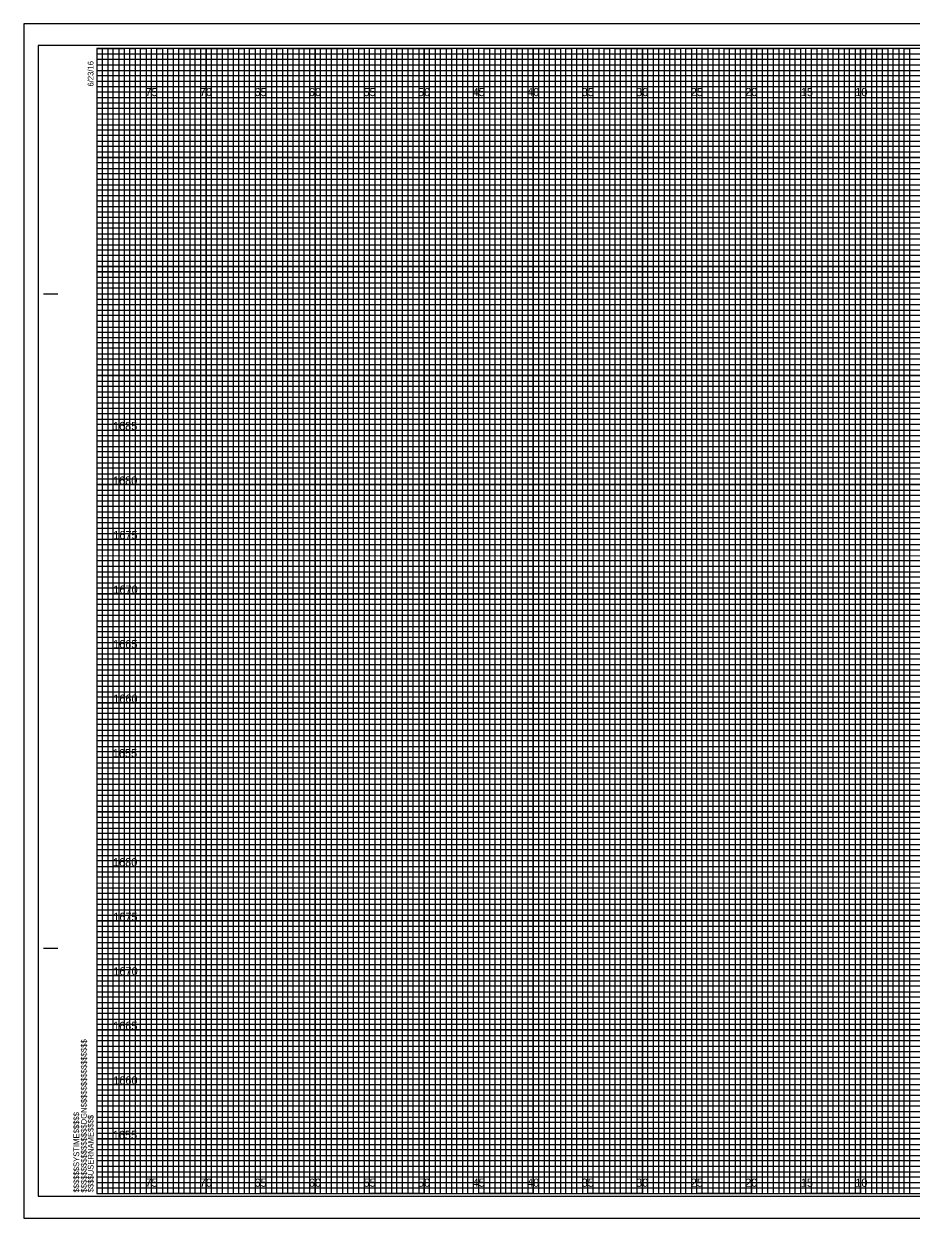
# Model space of a CAD drawing. Extents: x -73 to 95, y 6 to 446.
# Drawn here: x -73.1 to 8.2, y 226.1 to 335.6 of the extents above; entities that cross this region are included whole.
import ezdxf

# ---------------------------------------------------------------- set-up
doc = ezdxf.new("R2010")
doc.units = 0
for name, color, linetype in [('Exist CMT Alignment Centerline', 7, 'Continuous'), ('Prop Horizontal Alignment', 7, 'Continuous'), ('Prop XS DDE', 7, 'Continuous'), ('Raster_Level_0', 7, 'Continuous'), ('Sheet Cross Section CELL', 7, 'Continuous'), ('Sheet Cross Section Grid Minor 1 CELL', 7, 'Continuous'), ('Sheet Cross Section Grid Minor 2 CELL', 7, 'Continuous'), ('Sheet Cutting Line CELL', 7, 'Continuous'), ('Sheet DOT Grid CELL', 7, 'Continuous'), ('Sheet Plot Border Inside CELL', 7, 'Continuous'), ('Sheet Plot Border Outside CELL', 7, 'Continuous')]:
    doc.layers.add(name, color=color, linetype=linetype)

msp = doc.modelspace()

# ---------------------------------------------------------------- linework, layer by layer
at = {"layer": 'Exist CMT Alignment Centerline'}
for p, q in [((-61.4, 333.4), (-66.4, 333.4)), ((-61.4, 228.4), (-61.4, 333.4)), ((-51.4, 333.4), (-56.4, 333.4)), ((-56.4, 333.4), (-56.4, 228.4)), ((-51.4, 228.4), (-51.4, 333.4)), ((-41.4, 333.4), (-46.4, 333.4)), ((-46.4, 333.4), (-46.4, 228.4)), ((-41.4, 228.4), (-41.4, 333.4)), ((-31.4, 333.4), (-36.4, 333.4)), ((-36.4, 333.4), (-36.4, 228.4)), ((-31.4, 228.4), (-31.4, 333.4)), ((-21.4, 333.4), (-26.4, 333.4)), ((-26.4, 333.4), (-26.4, 228.4)), ((-21.4, 228.4), (-21.4, 333.4)), ((-11.4, 333.4), (-16.4, 333.4)), ((-16.4, 333.4), (-16.4, 228.4)), ((-11.4, 228.4), (-11.4, 333.4)), ((-1.4, 333.4), (-6.4, 333.4)), ((-6.4, 333.4), (-6.4, 228.4)), ((-1.4, 228.4), (-1.4, 333.4)), ((8.6, 333.4), (3.6, 333.4)), ((3.6, 333.4), (3.6, 228.4)), ((-56.4, 228.4), (-61.4, 228.4)), ((-46.4, 228.4), (-51.4, 228.4)), ((-36.4, 228.4), (-41.4, 228.4)), ((-26.4, 228.4), (-31.4, 228.4)), ((-16.4, 228.4), (-21.4, 228.4)), ((-6.4, 228.4), (-11.4, 228.4)), ((3.6, 228.4), (-1.4, 228.4))]:
    msp.add_line(p, q, dxfattribs=at)
for points in [[(-66.4, 328.4), (93.6, 328.4), (93.6, 323.4), (-66.4, 323.4)], [(-66.4, 318.4), (93.6, 318.4), (93.6, 313.4), (-66.4, 313.4)], [(-66.4, 308.4), (93.6, 308.4), (93.6, 303.4), (-66.4, 303.4)], [(-66.4, 298.4), (93.6, 298.4), (93.6, 293.4), (-66.4, 293.4)], [(-66.4, 288.4), (93.6, 288.4), (93.6, 283.4), (-66.4, 283.4)], [(-66.4, 278.4), (93.6, 278.4), (93.6, 273.4), (-66.4, 273.4)], [(-66.4, 268.4), (93.6, 268.4), (93.6, 263.4), (-66.4, 263.4)], [(-66.4, 258.4), (93.6, 258.4), (93.6, 253.4), (-66.4, 253.4)], [(-66.4, 248.4), (93.6, 248.4), (93.6, 243.4), (-66.4, 243.4)], [(-66.4, 238.4), (93.6, 238.4), (93.6, 233.4), (-66.4, 233.4)]]:
    msp.add_lwpolyline(points, dxfattribs=at)
at = {"layer": 'Prop XS DDE'}
for points in [[(-66.4, 333.4), (-63.9, 333.4), (-63.9, 228.4), (-58.9, 228.4), (-58.9, 333.4), (-53.9, 333.4), (-53.9, 228.4), (-48.9, 228.4), (-48.9, 333.4), (-43.9, 333.4), (-43.9, 228.4), (-38.9, 228.4), (-38.9, 333.4), (-33.9, 333.4), (-33.9, 228.4), (-28.9, 228.4), (-28.9, 333.4), (-23.9, 333.4), (-23.9, 228.4), (-18.9, 228.4), (-18.9, 333.4), (-13.9, 333.4), (-13.9, 228.4), (-8.9, 228.4), (-8.9, 333.4), (-3.9, 333.4), (-3.9, 228.4), (1.1, 228.4), (1.1, 333.4), (6.1, 333.4), (6.1, 228.4), (11.1, 228.4)], [(-66.4, 330.9), (71.1, 330.9)], [(-66.4, 320.9), (93.6, 320.9), (93.6, 325.9), (-66.4, 325.9)], [(-66.4, 310.9), (93.6, 310.9), (93.6, 315.9), (-66.4, 315.9)], [(-66.4, 300.9), (93.6, 300.9), (93.6, 305.9), (-66.4, 305.9)], [(-66.4, 290.9), (93.6, 290.9), (93.6, 295.9), (-66.4, 295.9)], [(-66.4, 280.9), (93.6, 280.9), (93.6, 285.9), (-66.4, 285.9)], [(-66.4, 270.9), (93.6, 270.9), (93.6, 275.9), (-66.4, 275.9)], [(-66.4, 260.9), (93.6, 260.9), (93.6, 265.9), (-66.4, 265.9)], [(-66.4, 250.9), (93.6, 250.9), (93.6, 255.9), (-66.4, 255.9)], [(-66.4, 240.9), (93.6, 240.9), (93.6, 245.9), (-66.4, 245.9)], [(-66.4, 230.9), (93.6, 230.9), (93.6, 235.9), (-66.4, 235.9)]]:
    msp.add_lwpolyline(points, dxfattribs=at)
at = {"layer": 'Sheet Cross Section CELL'}
for p, q in [((-71.3, 310.9), (-70.05, 310.9)), ((-71.25, 310.9), (-70, 310.9)), ((-71.3, 250.9), (-70.05, 250.9)), ((-71.25, 250.9), (-70, 250.9)), ((-66.4, 228.4), (-66.4, 228.4)), ((-66.4, 228.4), (-66.4, 228.4)), ((-66.4, 228.4), (-66.4, 228.4)), ((-66.4, 228.4), (-66.4, 228.4)), ((-66.4, 228.4), (-66.4, 228.4)), ((-66.4, 228.4), (-66.4, 228.4)), ((-66.4, 228.4), (-66.4, 228.4))]:
    msp.add_line(p, q, dxfattribs=at)
msp.add_lwpolyline([(93.6, 333.4), (-66.4, 333.4), (-66.4, 228.4), (93.6, 228.4)], close=True, dxfattribs=at)
at = {"layer": 'Sheet Cross Section Grid Minor 1 CELL'}
for p, q in [((-66.4, 332.9), (63.6, 332.9)), ((63.6, 332.39), (-66.4, 332.39)), ((-66.4, 332.39), (-66.4, 331.9)), ((-66.4, 331.9), (63.6, 331.9)), ((63.6, 331.34), (-66.4, 331.34)), ((-66.4, 331.34), (-66.4, 330.4)), ((-66.4, 330.4), (93.6, 330.4))]:
    msp.add_line(p, q, dxfattribs=at)
for points in [[(-66.4, 329.9), (68.6, 329.9), (93.6, 329.9), (93.6, 329.4), (-66.4, 329.4)], [(-66.4, 328.9), (93.6, 328.9), (93.6, 327.9), (-66.4, 327.9)], [(-66.4, 327.4), (93.6, 327.4), (93.6, 326.9), (-66.4, 326.89)], [(-66.4, 326.4), (93.6, 326.4), (93.6, 325.4), (-66.4, 325.4)], [(-66.4, 324.9), (93.6, 324.9), (93.6, 324.4), (-66.4, 324.4)], [(-66.4, 323.9), (93.6, 323.9), (93.6, 322.9), (-66.4, 322.9)], [(-66.4, 322.4), (93.6, 322.4), (93.6, 321.9), (-66.4, 321.9)], [(-66.4, 321.4), (93.6, 321.4), (93.6, 320.4), (-66.4, 320.4)], [(-66.4, 319.9), (93.6, 319.9), (93.6, 319.4), (-66.4, 319.4)], [(-66.4, 318.9), (93.6, 318.9), (93.6, 317.9), (-66.4, 317.9)], [(-66.4, 317.4), (93.6, 317.4), (93.6, 316.9), (-66.4, 316.9)], [(-66.4, 316.4), (93.6, 316.4), (93.6, 315.37), (93.6, 314.9), (93.6, 314.4), (-66.4, 314.4)], [(-66.4, 315.4), (93.6, 315.4), (93.6, 314.9), (-66.4, 314.9)], [(-66.4, 313.9), (93.6, 313.9), (93.6, 312.9), (-66.4, 312.91)], [(-66.4, 312.91), (93.6, 312.9), (93.6, 312.4), (-66.4, 312.4)], [(-66.4, 311.9), (93.6, 311.9), (93.6, 311.4), (-66.4, 311.4)], [(-66.4, 310.4), (93.6, 310.4), (93.6, 309.9), (-66.4, 309.9)], [(-66.4, 309.4), (93.6, 309.4), (93.6, 308.9), (-66.4, 308.9)], [(-66.43, 307.84), (93.6, 307.84), (93.6, 307.34), (-66.43, 307.34)], [(-66.4, 306.9), (93.6, 306.9), (93.6, 306.4), (-66.4, 306.4)], [(-66.4, 305.4), (93.6, 305.4), (93.6, 304.9), (-66.4, 304.9)], [(-66.4, 304.4), (93.6, 304.4), (93.6, 303.9), (-66.4, 303.9)], [(-66.4, 302.9), (93.6, 302.9), (93.6, 302.4), (-66.4, 302.4)], [(-66.4, 301.9), (93.6, 301.9), (93.6, 301.4), (-66.4, 301.4)], [(-66.4, 300.4), (93.6, 300.4), (93.6, 299.9), (-66.4, 299.9)], [(-66.4, 299.4), (93.6, 299.4), (93.6, 298.9), (-66.4, 298.9)], [(-66.4, 297.9), (93.6, 297.9), (93.6, 297.39), (-66.4, 297.4)], [(-66.4, 296.9), (93.6, 296.9), (93.6, 296.4), (-66.4, 296.4)], [(-66.4, 295.4), (93.6, 295.4), (93.6, 294.9), (-66.4, 294.9)], [(-66.4, 294.4), (93.6, 294.4), (93.6, 293.9), (-66.4, 293.9)], [(-66.4, 292.9), (93.6, 292.9), (93.6, 292.4), (-66.4, 292.4)], [(-66.4, 291.9), (93.6, 291.9), (93.6, 291.4), (-66.4, 291.4)], [(-66.4, 290.4), (93.6, 290.4), (93.6, 289.9), (-66.4, 289.9)], [(-66.4, 289.4), (93.6, 289.4), (93.6, 288.9), (-66.4, 288.9)], [(-66.4, 287.9), (93.6, 287.9), (93.6, 287.4), (-66.4, 287.4)], [(-66.4, 286.89), (93.64, 286.85), (93.6, 286.4), (-66.4, 286.4)], [(-66.4, 285.4), (93.6, 285.4), (93.6, 284.9), (-66.4, 284.9)], [(-66.4, 284.4), (93.6, 284.4), (93.6, 283.9), (-66.4, 283.9)], [(-66.4, 282.9), (93.6, 282.9), (93.6, 282.4), (-66.4, 282.4)], [(-66.4, 281.9), (93.6, 281.9), (93.6, 281.4), (-66.4, 281.4)], [(-66.4, 280.4), (93.6, 280.4), (93.6, 279.9), (-66.4, 279.9)], [(-66.4, 279.4), (93.6, 279.4), (93.6, 278.9), (-66.4, 278.9)], [(-66.4, 277.9), (93.6, 277.9), (93.6, 277.4), (-66.4, 277.4)], [(-66.4, 276.9), (93.6, 276.9), (93.6, 276.4), (-66.4, 276.4)], [(-66.4, 275.4), (93.6, 275.4), (93.6, 274.9), (-66.4, 274.9)], [(-66.4, 274.4), (93.6, 274.4), (93.6, 273.9), (-66.4, 273.9)], [(-66.4, 272.9), (93.6, 272.9), (93.6, 272.4), (-66.4, 272.4)], [(-66.4, 271.9), (93.6, 271.9), (93.6, 271.4), (-66.4, 271.4)], [(-66.4, 270.4), (93.6, 270.4), (93.6, 269.9), (-66.4, 269.9)], [(-66.4, 269.4), (93.6, 269.4), (93.6, 268.9), (-66.4, 268.9)], [(-66.4, 267.9), (93.6, 267.9), (93.6, 267.39), (-66.4, 267.4)], [(-66.4, 266.9), (93.6, 266.9), (93.6, 266.4), (-66.4, 266.4)], [(-66.4, 265.4), (93.6, 265.4), (93.6, 264.9), (-66.4, 264.9)], [(-66.4, 264.4), (93.6, 264.4), (93.6, 263.9), (-66.4, 263.9)], [(-66.4, 262.9), (93.6, 262.9), (93.6, 262.4), (-66.4, 262.4)], [(-66.4, 261.9), (93.6, 261.9), (93.6, 261.4), (-66.4, 261.4)], [(-66.4, 260.4), (93.6, 260.4), (93.6, 259.9), (-66.4, 259.9)], [(-66.4, 259.4), (93.6, 259.4), (93.6, 258.9), (-66.4, 258.9)], [(-66.4, 257.9), (93.6, 257.9), (93.6, 257.4), (-66.4, 257.4)], [(-66.4, 256.89), (93.64, 256.85), (93.6, 256.4), (-66.4, 256.4)], [(-66.4, 255.4), (93.6, 255.4), (93.6, 254.9), (-66.4, 254.9)], [(-66.4, 254.4), (93.6, 254.4), (93.6, 253.9), (-66.4, 253.9)], [(-66.4, 252.9), (93.6, 252.9), (93.6, 252.4), (-66.4, 252.4)], [(-66.4, 251.9), (93.6, 251.9), (93.6, 251.4), (-66.4, 251.4)], [(-66.4, 250.4), (93.6, 250.4), (93.6, 249.9), (-66.4, 249.9)], [(-66.4, 249.4), (93.6, 249.4), (93.6, 248.9), (-66.4, 248.9)], [(-66.4, 247.9), (93.6, 247.9), (93.6, 247.4), (-66.4, 247.4)], [(-66.4, 246.9), (93.6, 246.9), (93.6, 246.4), (-66.4, 246.4)], [(-66.4, 245.4), (93.6, 245.4), (93.6, 244.9), (-66.4, 244.9)], [(-66.4, 244.4), (93.6, 244.4), (93.6, 243.9), (-66.4, 243.9)], [(-66.4, 242.9), (93.6, 242.9), (93.6, 242.4), (-66.4, 242.4)], [(-66.4, 241.9), (93.6, 241.9), (93.6, 241.4), (-66.4, 241.4)], [(-66.4, 240.4), (93.6, 240.4), (93.6, 239.9), (-66.4, 239.9)], [(-66.4, 239.4), (93.6, 239.4), (93.6, 238.9), (-66.4, 238.9)], [(-66.4, 237.9), (93.6, 237.9), (93.6, 237.4), (-66.4, 237.4)], [(-66.4, 236.9), (93.6, 236.9), (93.6, 236.4), (-66.4, 236.4)], [(-66.4, 235.4), (93.6, 235.4), (93.6, 234.9), (-66.4, 234.9)], [(-66.4, 234.4), (93.6, 234.4), (93.6, 233.9), (-66.4, 233.9)], [(-66.4, 232.9), (93.6, 232.9), (93.6, 232.4), (-66.4, 232.4)], [(-66.4, 231.9), (93.6, 231.9), (93.6, 231.4), (-66.4, 231.4)], [(-66.4, 230.4), (93.6, 230.4), (93.6, 229.9), (-66.4, 229.9)], [(-66.4, 229.4), (93.6, 229.4), (93.6, 228.9), (-66.4, 228.9)]]:
    msp.add_lwpolyline(points, dxfattribs=at)
at = {"layer": 'Sheet Cross Section Grid Minor 2 CELL'}
for points in [[(-66.4, 228.4), (-65.9, 228.4), (-65.9, 333.4), (-65.4, 333.4), (-65.4, 228.4)], [(-65.4, 228.4), (-64.9, 228.4), (-64.9, 333.4), (-64.4, 333.4), (-64.4, 228.4)], [(-63.9, 228.4), (-63.4, 228.4), (-63.4, 333.4), (-62.9, 333.4), (-62.9, 228.4)], [(-62.9, 228.4), (-62.4, 228.4), (-62.4, 333.4), (-61.9, 333.4), (-61.9, 228.4)], [(-61.4, 228.4), (-60.9, 228.4), (-60.9, 333.4), (-60.4, 333.4), (-60.4, 228.4)], [(-60.4, 228.4), (-59.9, 228.4), (-59.9, 333.4), (-59.4, 333.4), (-59.4, 228.4)], [(-58.9, 228.4), (-58.4, 228.4), (-58.4, 333.4), (-57.9, 333.4), (-57.9, 228.4)], [(-57.9, 228.4), (-57.4, 228.4), (-57.4, 333.4), (-56.9, 333.4), (-56.9, 228.4)], [(-56.4, 228.4), (-55.9, 228.4), (-55.9, 333.4), (-55.4, 333.4), (-55.4, 228.4)], [(-55.4, 228.4), (-54.9, 228.4), (-54.9, 333.4), (-54.4, 333.4), (-54.4, 228.4)], [(-53.9, 228.4), (-53.4, 228.4), (-53.4, 333.4), (-52.9, 333.4), (-52.9, 228.4)], [(-52.9, 228.4), (-52.4, 228.4), (-52.4, 333.4), (-51.9, 333.4), (-51.9, 228.4)], [(-51.4, 228.4), (-50.9, 228.4), (-50.9, 333.4), (-50.4, 333.4), (-50.4, 228.4)], [(-50.4, 228.4), (-49.9, 228.4), (-49.9, 333.4), (-49.4, 333.4), (-49.4, 228.4)], [(-48.9, 228.4), (-48.4, 228.4), (-48.4, 333.4), (-47.9, 333.4), (-47.9, 228.4)], [(-47.9, 228.4), (-47.4, 228.4), (-47.4, 333.4), (-46.9, 333.4), (-46.9, 228.4)], [(-46.4, 228.4), (-45.9, 228.4), (-45.9, 333.4), (-45.4, 333.4), (-45.4, 228.4)], [(-45.4, 228.4), (-44.9, 228.4), (-44.9, 333.4), (-44.4, 333.4), (-44.4, 228.4)], [(-43.9, 228.4), (-43.4, 228.4), (-43.4, 333.4), (-42.9, 333.4), (-42.9, 228.4)], [(-42.9, 228.4), (-42.4, 228.4), (-42.4, 333.4), (-41.9, 333.4), (-41.9, 228.4)], [(-41.4, 228.4), (-40.9, 228.4), (-40.9, 333.4), (-40.4, 333.4), (-40.4, 228.4)], [(-40.4, 228.4), (-39.9, 228.4), (-39.9, 333.4), (-39.4, 333.4), (-39.4, 228.4)], [(-38.9, 228.4), (-38.4, 228.4), (-38.4, 333.4), (-37.9, 333.4), (-37.9, 228.4)], [(-37.9, 228.4), (-37.4, 228.4), (-37.4, 333.4), (-36.9, 333.4), (-36.9, 228.4)], [(-36.4, 228.4), (-35.9, 228.4), (-35.9, 333.4), (-35.4, 333.4), (-35.4, 228.4)], [(-35.4, 228.4), (-34.9, 228.4), (-34.9, 333.4), (-34.4, 333.4), (-34.4, 228.4)], [(-33.9, 228.4), (-33.4, 228.4), (-33.4, 333.4), (-32.9, 333.4), (-32.9, 228.4)], [(-32.9, 228.4), (-32.4, 228.4), (-32.4, 333.4), (-31.9, 333.4), (-31.9, 228.4)], [(-31.4, 228.4), (-30.9, 228.4), (-30.9, 333.4), (-30.4, 333.4), (-30.4, 228.4)], [(-30.4, 228.4), (-29.9, 228.4), (-29.9, 333.4), (-29.4, 333.4), (-29.4, 228.4)], [(-28.9, 228.4), (-28.4, 228.4), (-28.4, 333.4), (-27.9, 333.4), (-27.9, 228.4)], [(-27.9, 228.4), (-27.4, 228.4), (-27.4, 333.4), (-26.9, 333.4), (-26.9, 228.4)], [(-26.4, 228.4), (-25.9, 228.4), (-25.9, 333.4), (-25.4, 333.4), (-25.4, 228.4)], [(-25.4, 228.4), (-24.9, 228.4), (-24.9, 333.4), (-24.4, 333.4), (-24.4, 228.4)], [(-23.9, 228.4), (-23.4, 228.4), (-23.4, 333.4), (-22.9, 333.4), (-22.9, 228.4)], [(-22.9, 228.4), (-22.4, 228.4), (-22.4, 333.4), (-21.9, 333.4), (-21.9, 228.4)], [(-21.4, 228.4), (-20.9, 228.4), (-20.9, 333.4), (-20.4, 333.4), (-20.4, 228.4)], [(-20.4, 228.4), (-19.9, 228.4), (-19.9, 333.4), (-19.4, 333.4), (-19.4, 228.4)], [(-18.9, 228.4), (-18.4, 228.4), (-18.4, 333.4), (-17.9, 333.4), (-17.9, 228.4)], [(-17.9, 228.4), (-17.4, 228.4), (-17.4, 333.4), (-16.9, 333.4), (-16.9, 228.4)], [(-16.4, 228.4), (-15.9, 228.4), (-15.9, 333.4), (-15.4, 333.4), (-15.4, 228.4)], [(-15.4, 228.4), (-14.9, 228.4), (-14.9, 333.4), (-14.4, 333.4), (-14.4, 228.4)], [(-13.9, 228.4), (-13.4, 228.4), (-13.4, 333.4), (-12.9, 333.4), (-12.9, 228.4)], [(-12.9, 228.4), (-12.4, 228.4), (-12.4, 333.4), (-11.9, 333.4), (-11.9, 228.4)], [(-11.4, 228.4), (-10.9, 228.4), (-10.9, 333.4), (-10.4, 333.4), (-10.4, 228.4)], [(-10.4, 228.4), (-9.9, 228.4), (-9.9, 333.4), (-9.4, 333.4), (-9.4, 228.4)], [(-8.9, 228.4), (-8.4, 228.4), (-8.4, 333.4), (-7.9, 333.4), (-7.9, 228.4)], [(-7.9, 228.4), (-7.4, 228.4), (-7.4, 333.4), (-6.9, 333.4), (-6.9, 228.4)], [(-6.4, 228.4), (-5.9, 228.4), (-5.9, 333.4), (-5.4, 333.4), (-5.4, 228.4)], [(-5.4, 228.4), (-4.9, 228.4), (-4.9, 333.4), (-4.4, 333.4), (-4.4, 228.4)], [(-3.9, 228.4), (-3.4, 228.4), (-3.4, 333.4), (-2.9, 333.4), (-2.9, 228.4)], [(-2.9, 228.4), (-2.4, 228.4), (-2.4, 333.4), (-1.9, 333.4), (-1.9, 228.4)], [(-1.4, 228.4), (-0.9, 228.4), (-0.9, 333.4), (-0.4, 333.4), (-0.4, 228.4)], [(-0.4, 228.4), (0.1, 228.4), (0.1, 333.4), (0.6, 333.4), (0.6, 228.4)], [(1.1, 228.4), (1.6, 228.4), (1.6, 333.4), (2.1, 333.4), (2.1, 228.4)], [(2.1, 228.4), (2.6, 228.4), (2.6, 333.4), (3.1, 333.4), (3.1, 228.4)], [(3.6, 228.4), (4.1, 228.4), (4.1, 333.4), (4.6, 333.4), (4.6, 228.4)], [(4.6, 228.4), (5.1, 228.4), (5.1, 333.4), (5.6, 333.4), (5.6, 228.4)], [(6.1, 228.4), (6.6, 228.4), (6.6, 333.4), (7.1, 333.4), (7.1, 228.4)], [(7.1, 228.4), (7.6, 228.4), (7.6, 333.4), (8.1, 333.4), (8.1, 228.4)]]:
    msp.add_lwpolyline(points, dxfattribs=at)
at = {"layer": 'Sheet Cutting Line CELL'}
for p, q in [((95.25, 335.65), (-73.1, 335.65)), ((-73.1, 335.65), (-73.1, 226.15)), ((-73.1, 226.15), (95.25, 226.15))]:
    msp.add_line(p, q, dxfattribs=at)
at = {"layer": 'Sheet DOT Grid CELL'}
for p, q in [((-61.4, 228.4), (-61.4, 333.4)), ((-56.4, 228.4), (-56.4, 333.4)), ((-51.4, 228.4), (-51.4, 333.4)), ((-46.4, 228.4), (-46.4, 333.4)), ((-41.4, 228.4), (-41.4, 333.4)), ((-36.4, 228.4), (-36.4, 333.4)), ((-31.4, 228.4), (-31.4, 333.4)), ((-26.4, 228.4), (-26.4, 333.4)), ((-21.4, 228.4), (-21.4, 333.4)), ((-16.4, 228.4), (-16.4, 333.4)), ((-11.4, 228.4), (-11.4, 333.4)), ((-6.4, 228.4), (-6.4, 333.4)), ((-1.4, 228.4), (-1.4, 333.4)), ((3.6, 228.4), (3.6, 333.4)), ((-66.4, 328.4), (93.6, 328.4)), ((-66.4, 323.4), (93.6, 323.4)), ((-66.4, 318.4), (93.6, 318.4)), ((-66.4, 313.4), (93.6, 313.4)), ((-66.4, 308.4), (93.6, 308.4)), ((-66.4, 303.4), (93.6, 303.4)), ((-66.4, 298.4), (93.6, 298.4)), ((-66.4, 293.4), (93.6, 293.4)), ((-66.4, 288.4), (93.6, 288.4)), ((-66.4, 283.4), (93.6, 283.4)), ((-66.4, 278.4), (93.6, 278.4)), ((-66.4, 273.4), (93.6, 273.4)), ((-66.4, 268.4), (93.6, 268.4)), ((-66.4, 263.4), (93.6, 263.4)), ((-66.4, 258.4), (93.6, 258.4)), ((-66.4, 253.4), (93.6, 253.4)), ((-66.4, 248.4), (93.6, 248.4)), ((-66.4, 243.4), (93.6, 243.4)), ((-66.4, 238.4), (93.6, 238.4)), ((-66.4, 233.4), (93.6, 233.4))]:
    msp.add_line(p, q, dxfattribs=at)
at = {"layer": 'Sheet Plot Border Inside CELL'}
msp.add_lwpolyline([(-71.8, 228.15), (94.8, 228.15), (94.8, 333.65), (-71.8, 333.65)], close=True, dxfattribs=at)
at = {"layer": 'Sheet Plot Border Outside CELL'}
msp.add_lwpolyline([(-73.1, 226.15), (95.25, 226.15), (95.25, 335.65), (-73.1, 335.65)], close=True, dxfattribs=at)

# ---------------------------------------------------------------- texts
at = {"layer": 'Prop Horizontal Alignment'}
for s, p in [('1685', (-64.93, 298.4)), ('1680', (-64.93, 293.4)), ('1675', (-64.91, 288.4)), ('1670', (-64.9, 283.4)), ('1665', (-64.92, 278.4)), ('1660', (-64.91, 273.4)), ('1655', (-64.95, 268.4)), ('1680', (-64.93, 258.4)), ('1675', (-64.91, 253.4)), ('1670', (-64.9, 248.4)), ('1665', (-64.92, 243.4)), ('1660', (-64.91, 238.4)), ('1655', (-64.95, 233.4))]:
    msp.add_text(s, height=0.75, dxfattribs=at).set_placement(p)
at = {"layer": 'Raster_Level_0'}
for s, p in [('75', (-61.96, 329.02)), ('70', (-56.97, 329.02)), ('65', (-51.96, 329.02)), ('60', (-46.97, 329.02)), ('55', (-41.96, 329.02)), ('50', (-36.97, 329.02)), ('45', (-31.96, 329.02)), ('40', (-26.97, 329.02)), ('35', (-21.96, 329.02)), ('30', (-16.97, 329.02)), ('25', (-11.96, 329.02)), ('20', (-6.97, 329.02)), ('15', (-1.87, 329.02)), ('10', (3.12, 329.02)), ('75', (-61.96, 229.02)), ('70', (-56.97, 229.02)), ('65', (-51.96, 229.02)), ('60', (-46.97, 229.02)), ('55', (-41.96, 229.02)), ('50', (-36.97, 229.02)), ('45', (-31.96, 229.02)), ('40', (-26.97, 229.02)), ('35', (-21.96, 229.02)), ('30', (-16.97, 229.02)), ('25', (-11.96, 229.02)), ('20', (-6.97, 229.02)), ('15', (-1.87, 229.02)), ('10', (3.12, 229.02))]:
    msp.add_text(s, height=0.75, dxfattribs=at).set_placement(p)
at = {"layer": 'Sheet Cross Section CELL'}
for s, p in [('6/23/16', (-66.72, 329.9)), ('$$$$$$$$$$$$$$$$DGN$$$$$$$$$$$$$$$$', (-67.34, 228.49)), ('$$$$$$SYSTIME$$$$$', (-68.03, 228.49)), ('$$$$USERNAME$$$$', (-66.71, 228.51))]:
    msp.add_text(s, height=0.525, rotation=90, dxfattribs=at).set_placement(p)

doc.saveas('drawing.dxf')
